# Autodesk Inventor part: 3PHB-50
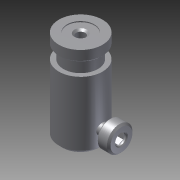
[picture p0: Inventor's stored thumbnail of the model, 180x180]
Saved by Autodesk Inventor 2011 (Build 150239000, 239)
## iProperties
Created: 2011-07
Part Number: 3PHB-50
Document SubType Name: Modeling
Designer: vadybininkas6
Density: 1 g/cm^3
Author: vadybininkas6
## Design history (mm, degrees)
feature "Base1"
body "Solid1"
